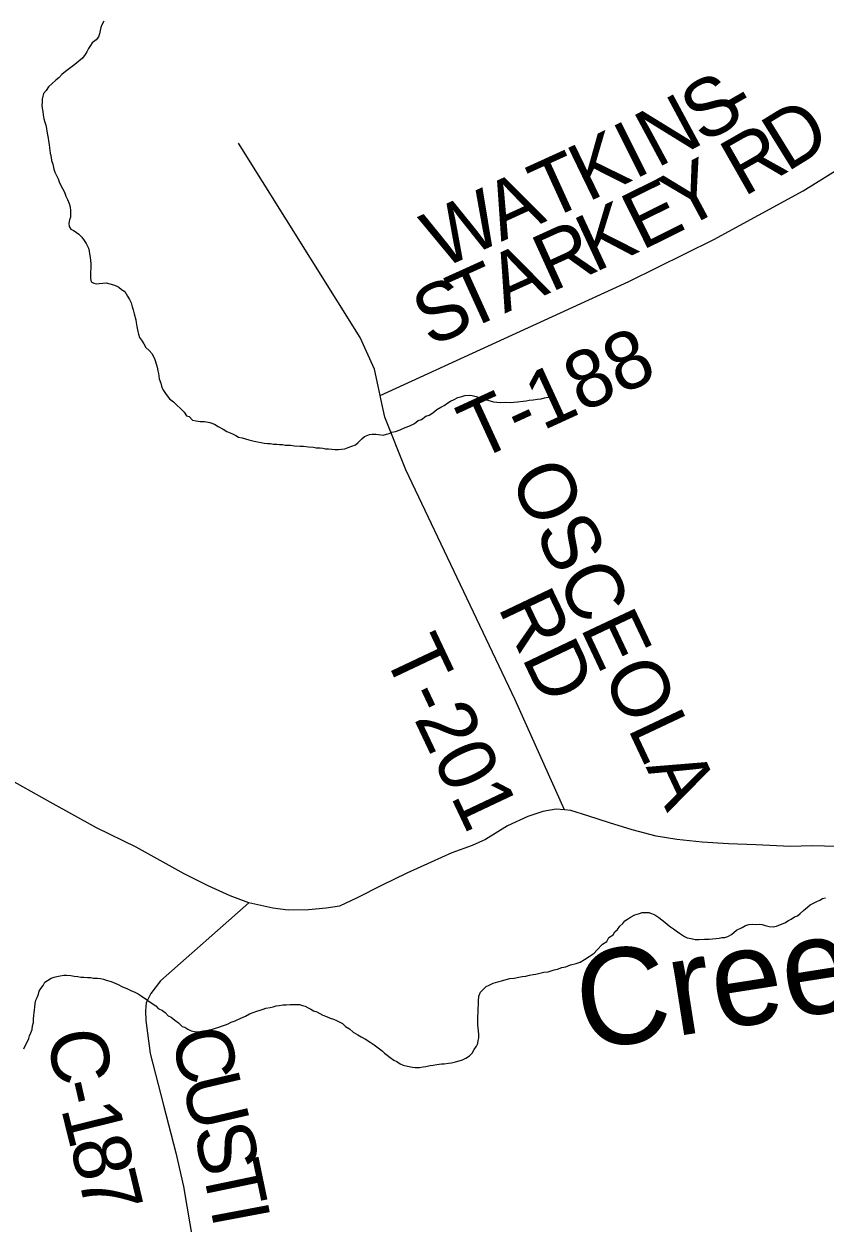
# Model space of a CAD drawing. Extents: x 1310247 to 1664935, y 284496 to 704931.
# Drawn here: x 1532360 to 1536534, y 478494 to 484741 of the extents above; entities that cross this region are included whole.
import ezdxf

# ---------------------------------------------------------------- set-up
doc = ezdxf.new("R2010")
doc.units = 0
for name, color, linetype in [('GM_X_County_Road_Text', 7, 'Continuous'), ('GM_X_County_Subdivision_Text', 7, 'Continuous'), ('GM_X_Interstate_Shield', 7, 'Continuous'), ('GM_X_Minor_Lake_Text', 7, 'Continuous'), ('GM_X_Minor_River_Text', 7, 'Continuous'), ('GM_X_Township_Road', 7, 'Continuous'), ('GM_X_Township_Subdivision', 7, 'Continuous')]:
    doc.layers.add(name, color=color, linetype=linetype)

msp = doc.modelspace()

# ---------------------------------------------------------------- linework, layer by layer
at = {"layer": 'GM_X_County_Road_Text'}
msp.add_lwpolyline([(1533530.8, 480162), (1533071, 479755.7), (1533021.5, 479690.4), (1532996.3, 479640.8), (1532993.5, 479598.7), (1532994.4, 479548.5), (1533017, 479377.6), (1533087.7, 479107.3), (1533150.9, 478859.2), (1533191.5, 478683.8), (1533241.6, 478387.9), (1533278.3, 478220.6), (1533348.3, 478040.9), (1533474.4, 477797.3), (1534173.6, 476597.1), (1537612.9, 470693.1)], dxfattribs=at)
at = {"layer": 'GM_X_County_Subdivision_Text'}
for points in [[(1534215.7, 482805.9), (1535511.9, 483398.7), (1535955.2, 483618.4), (1536419.1, 483871.9), (1536599.6, 483983.4), (1536717.8, 484091.9), (1536773.5, 484189.3), (1536863, 484260.1), (1537210.2, 484369), (1537644, 484625)], [(1534205.6, 482853.7), (1534187.1, 482941.9), (1534111.4, 483107.6), (1533478.3, 484120.1)], [(1535176.4, 480646.2), (1534919.6, 481219.8), (1534349.7, 482418), (1534239.5, 482692.4), (1534219.6, 482787.2), (1534215.7, 482805.9), (1534205.6, 482853.7)]]:
    msp.add_lwpolyline(points, dxfattribs=at)
at = {"layer": 'GM_X_Interstate_Shield'}
msp.add_lwpolyline([(1536596.3, 480455.1), (1536465.4, 480458.8), (1536354.6, 480455.9), (1536173.6, 480465), (1536030.7, 480469), (1535894, 480478.9), (1535761.5, 480492.6), (1535653.2, 480509.7), (1535529.3, 480543.3), (1535411.5, 480578.8), (1535297.7, 480616.1), (1535209.9, 480642.6), (1535176.4, 480646.2), (1535133.6, 480650.8), (1535062.7, 480638.8), (1534985.5, 480612.8), (1534879.3, 480563.6), (1534764.6, 480492.6), (1534695.2, 480460.4), (1534589.4, 480423.3), (1534481.3, 480374.1), (1534354.8, 480317.4), (1534222.1, 480252.9), (1534095.4, 480188.2), (1534003.5, 480144.6), (1533934.8, 480134.5), (1533841.9, 480125.1), (1533737.1, 480124), (1533656.8, 480134.3), (1533530.8, 480162), (1533435.1, 480198.8), (1533319.7, 480250.2), (1533194.7, 480313.9), (1532944.8, 480451.4), (1532738.2, 480553.6), (1532496.2, 480686.9), (1532254.4, 480822.1)], dxfattribs=at)
at = {"layer": 'GM_X_Minor_River_Text'}
for points in [[(1532775.8, 484754.9), (1532765.3, 484737.1), (1532760.9, 484723.2), (1532756.5, 484707.2), (1532754, 484689.2), (1532747.6, 484673.3), (1532735.2, 484657.6), (1532714.7, 484642), (1532706.3, 484628.2), (1532695.9, 484612.4), (1532687.5, 484596.5), (1532679.1, 484582.7), (1532664.5, 484563), (1532646, 484547.3), (1532625.5, 484529.8), (1532611.2, 484520.1), (1532596.9, 484508.4), (1532576.4, 484492.8), (1532557.9, 484477.2), (1532541.4, 484459.6), (1532525.1, 484447.9), (1532506.5, 484430.3), (1532488, 484412.7), (1532475.5, 484395), (1532461.1, 484379.3), (1532458.7, 484365.3), (1532454.3, 484349.3), (1532453.9, 484333.3), (1532453.5, 484317.2), (1532455.2, 484303.2), (1532458.7, 484285), (1532460.3, 484266.9), (1532463.8, 484246.8), (1532469.4, 484228.6), (1532473, 484214.4), (1532476.6, 484196.3), (1532478.3, 484182.2), (1532481.8, 484164.1), (1532485.4, 484145.9), (1532487, 484131.8), (1532490.6, 484113.7), (1532492.2, 484095.6), (1532493.8, 484081.5), (1532495.5, 484067.4), (1532501, 484045.2), (1532502.6, 484029.1), (1532510.2, 484010.9), (1532515.5, 483984.7), (1532521.2, 483968.5), (1532526.8, 483954.3), (1532538.4, 483934), (1532544, 483917.8), (1532551.6, 483899.5), (1532561.2, 483883.3), (1532570.8, 483865), (1532578.4, 483844.7), (1532585.9, 483826.5), (1532595.5, 483806.2), (1532601, 483788), (1532602.6, 483767.9), (1532602.1, 483747.8), (1532601.7, 483733.8), (1532597.3, 483719.9), (1532592.9, 483703.9), (1532594.5, 483685.8), (1532604.2, 483671.5), (1532622, 483663.1), (1532645.7, 483646.5)], [(1532645.7, 483646.5), (1532661.4, 483630), (1532673, 483613.7), (1532684.7, 483597.4), (1532696.1, 483573), (1532699.8, 483556.9), (1532701.4, 483542.8), (1532705, 483524.6), (1532706.6, 483510.6), (1532708.2, 483490.5), (1532707.6, 483466.4), (1532707.2, 483450.3), (1532706.7, 483430.3), (1532706.3, 483414.3), (1532709.9, 483398.1), (1532723.7, 483389.8), (1532737.7, 483387.4), (1532751.8, 483389.1), (1532770, 483390.7), (1532788.1, 483392.2), (1532808.1, 483387.7), (1532826, 483381.3), (1532839.9, 483376.9), (1532853.8, 483370.6), (1532867.6, 483358.2), (1532885.4, 483347.8), (1532898.9, 483323.3), (1532910.5, 483305), (1532918.1, 483288.8), (1532923.6, 483266.6), (1532929.2, 483252.4), (1532934.7, 483230.2), (1532942, 483199.9), (1532943.7, 483185.8), (1532947.2, 483165.7), (1532952.6, 483139.5), (1532956.2, 483125.3), (1532961.8, 483107.1), (1532971.5, 483092.8), (1532985.1, 483074.5), (1532994.7, 483056.2), (1533012.3, 483039.7), (1533028, 483023.3), (1533041.3, 482992.8), (1533048.8, 482970.6), (1533054.4, 482952.4), (1533057.9, 482934.3), (1533061.6, 482920.1), (1533063.3, 482906), (1533064.9, 482892), (1533072.4, 482869.7), (1533077.9, 482847.5), (1533087.5, 482831.2), (1533101.1, 482810.8), (1533118.6, 482788.3), (1533138.3, 482771.8), (1533155.9, 482755.3), (1533175.6, 482736.8), (1533195.2, 482718.3), (1533206.8, 482699.9), (1533220.8, 482695.6), (1533238.4, 482677.1), (1533256.3, 482672.6), (1533278.4, 482670.1), (1533300.5, 482669.6), (1533328.5, 482664.9), (1533352.4, 482656.3), (1533372.1, 482643.8), (1533397.9, 482629.1), (1533417.7, 482618.6), (1533433.6, 482610.2), (1533449.5, 482603.8), (1533463.4, 482597.4), (1533477.3, 482589.1), (1533497.2, 482584.6), (1533531.1, 482573.7), (1533559.1, 482567), (1533577.1, 482564.6), (1533595.1, 482560.1), (1533611.1, 482557.8), (1533629.1, 482555.3), (1533643.1, 482555), (1533659.2, 482552.6), (1533677.2, 482552.1), (1533691.2, 482549.8), (1533707.3, 482549.4), (1533721.3, 482547.1), (1533749.4, 482546.4), (1533769.4, 482543.9), (1533799.5, 482541.2), (1533815.6, 482540.8), (1533841.6, 482538.1), (1533867.7, 482535.5), (1533881.7, 482533.2), (1533903.8, 482532.6), (1533917.8, 482530.3), (1533931.8, 482527.9), (1533945.8, 482527.6), (1533963.8, 482525.2), (1533979.9, 482524.8), (1533998, 482524.3)], [(1533998, 482524.3), (1534014.1, 482526), (1534032.2, 482527.5), (1534048.5, 482535.2), (1534068.7, 482540.7), (1534086.9, 482548.3), (1534101.3, 482560), (1534119.9, 482579.6), (1534134.2, 482591.3), (1534160.6, 482602.7), (1534174.7, 482604.3), (1534192.8, 482603.9), (1534206.8, 482601.6), (1534230.8, 482599), (1534249.1, 482604.6), (1534263.2, 482608.2), (1534277.4, 482613.9), (1534295.6, 482617.5), (1534319.9, 482626.9), (1534346.3, 482638.3), (1534370.7, 482647.8), (1534395.1, 482659.2), (1534413.5, 482674.8), (1534431.7, 482680.4), (1534454.3, 482697.9), (1534470.5, 482703.5), (1534490.9, 482715.1), (1534511.4, 482732.7), (1534531.8, 482744.2), (1534550.1, 482753.8), (1534568.5, 482767.4), (1534582.8, 482775.1), (1534601.1, 482784.7), (1534621.4, 482794.2), (1534641.6, 482799.8), (1534657.8, 482805.4), (1534680, 482806.8), (1534696, 482804.5), (1534716, 482800), (1534735.9, 482793.5), (1534761.8, 482784.8), (1534777.7, 482780.4), (1534805.7, 482771.7), (1534823.7, 482771.3), (1534843.7, 482768.8), (1534867.9, 482770.2), (1534894, 482769.6), (1534912.1, 482771.1), (1534932.2, 482772.7), (1534960.4, 482776), (1534976.6, 482777.6), (1534992.7, 482781.2), (1535012.8, 482782.8), (1535035, 482786.2), (1535055.1, 482787.8), (1535071.4, 482793.4), (1535091.5, 482796.9), (1535105.7, 482800.6)], [(1536028.2, 479987.3), (1536046.6, 479996.9), (1536073.3, 480020.3), (1536101.7, 480033.7), (1536120, 480043.2), (1536136.2, 480048.9), (1536154.4, 480050.5), (1536176.5, 480049.9), (1536192.6, 480051.5), (1536206.6, 480049.2), (1536222.5, 480044.8), (1536242.5, 480038.3), (1536264.5, 480037.8), (1536280.7, 480041.4), (1536301, 480048.9), (1536325.3, 480058.4), (1536343.7, 480070), (1536357.9, 480077.6), (1536374.3, 480089.3), (1536390.5, 480094.9), (1536404.9, 480106.6), (1536421.3, 480122.3), (1536441.8, 480139.8), (1536456.2, 480151.5), (1536474.5, 480161.1), (1536490.8, 480168.7), (1536507, 480176.4), (1536521.3, 480184.1), (1536535.5, 480187.7)], [(1534398.1, 479304.3), (1534420.2, 479303.7), (1534440.4, 479307.2), (1534454.5, 479308.9), (1534476.7, 479314.4), (1534492.8, 479316), (1534511, 479319.6), (1534535.2, 479323), (1534549.2, 479322.7), (1534571.4, 479326.2), (1534587.5, 479327.8), (1534607.8, 479333.3), (1534628, 479338.8), (1534644.2, 479344.5), (1534662.5, 479352.1), (1534680.9, 479365.7), (1534695.3, 479379.4), (1534705.8, 479397.2), (1534718.3, 479414.9), (1534724.6, 479428.8), (1534727.1, 479444.8), (1534729.4, 479458.8), (1534729.9, 479476.8), (1534728.3, 479494.9), (1534726.7, 479511), (1534725.1, 479527.1), (1534725.5, 479545.2), (1534724.2, 479571.3), (1534726.6, 479589.3), (1534727.2, 479613.3), (1534727.7, 479631.4), (1534728.1, 479649.4), (1534730.8, 479675.5), (1534739.4, 479697.3), (1534753.8, 479713), (1534768.2, 479726.7), (1534784.4, 479732.4), (1534804.8, 479743.9), (1534829.1, 479751.3), (1534855.3, 479756.7), (1534871.6, 479762.4), (1534891.8, 479767.9), (1534913.9, 479769.4), (1534938.2, 479774.8), (1534956.3, 479778.4), (1534974.4, 479780), (1534994.7, 479785.5), (1535012.8, 479789.1), (1535026.9, 479790.7), (1535041.1, 479794.4), (1535069.4, 479801.7), (1535091.5, 479803.2), (1535121.9, 479812.5), (1535140.1, 479816.1), (1535162.4, 479825.6), (1535182.6, 479829.1), (1535206.9, 479838.5), (1535237.2, 479845.8), (1535257.5, 479853.4), (1535280, 479866.9), (1535304.4, 479882.3), (1535331, 479899.8), (1535345.4, 479915.5), (1535374.3, 479946.9), (1535396.8, 479960.4), (1535407.4, 479982.2), (1535429.8, 479995.7), (1535438.2, 480011.5), (1535452.6, 480023.2), (1535465.1, 480041), (1535479.5, 480054.7), (1535489.9, 480068.5), (1535504.1, 480076.2), (1535520.5, 480087.8), (1535542.9, 480099.3), (1535567.2, 480106.8), (1535581.4, 480112.4), (1535595.4, 480112.1), (1535615.5, 480111.6), (1535629.4, 480107.3), (1535647.3, 480098.8), (1535667.1, 480086.3), (1535682.9, 480073.9), (1535698.6, 480061.4), (1535712.4, 480049.1), (1535728.1, 480036.7), (1535744, 480026.2), (1535757.8, 480015.9), (1535775.5, 480003.4), (1535801.2, 479986.7), (1535815.1, 479980.4), (1535837.1, 479975.8), (1535857.1, 479971.3), (1535877.2, 479970.9), (1535905.3, 479972.2), (1535929.5, 479973.6), (1535947.6, 479975.2), (1535981.8, 479978.4), (1535996, 479982), (1536012, 479981.6), (1536028.2, 479987.3)], [(1532359.5, 479401.6), (1532370.1, 479423.4), (1532378.5, 479439.3), (1532384.9, 479455.2), (1532389.3, 479469.1), (1532395.7, 479485), (1532402.2, 479502.9), (1532404.6, 479520.9), (1532409.1, 479538.9), (1532409.5, 479556.9), (1532412, 479574.9), (1532412.3, 479589), (1532414.7, 479604.9), (1532417.1, 479618.9), (1532417.5, 479637), (1532422, 479654.9), (1532428.4, 479668.8), (1532434.9, 479686.7), (1532439.3, 479702.7), (1532447.6, 479716.5), (1532460.1, 479732.3), (1532468.5, 479748.1), (1532482.8, 479757.8), (1532501.2, 479769.4), (1532517.4, 479775), (1532531.6, 479778.7), (1532547.7, 479782.3)], [(1532547.7, 479782.3), (1532567.9, 479785.8), (1532582, 479785.5), (1532604, 479783), (1532622, 479780.5), (1532640, 479778.1), (1532656, 479775.7), (1532672.1, 479775.3), (1532690.1, 479772.9), (1532708.2, 479772.4), (1532722.2, 479770.1), (1532742.3, 479769.6), (1532758.3, 479767.2), (1532774.3, 479764.8), (1532788.2, 479758.5), (1532814.2, 479751.8), (1532849.9, 479736.9), (1532869.8, 479726.4), (1532899.6, 479713.6), (1532919.4, 479703.1), (1532933.4, 479698.8), (1532955.2, 479688.2), (1532971, 479677.8), (1532998.7, 479659.1), (1533012.5, 479648.7), (1533046.1, 479625.8), (1533059.8, 479611.5), (1533081.6, 479600.9), (1533095.4, 479590.5), (1533111.1, 479574.1), (1533126.9, 479565.7), (1533146.7, 479551.2), (1533164.4, 479536.7), (1533184, 479518.1), (1533198, 479513.8), (1533213.8, 479503.4), (1533231.7, 479494.9), (1533247.7, 479492.5), (1533261.7, 479490.2), (1533277.8, 479491.8), (1533297.9, 479493.3), (1533324.2, 479500.7), (1533342.4, 479504.3), (1533358.6, 479509.9), (1533374.8, 479513.6), (1533388.9, 479519.2), (1533409.2, 479526.8), (1533423.4, 479532.5), (1533439.7, 479540.1), (1533460, 479547.6), (1533490.4, 479560.9), (1533514.8, 479572.4), (1533535.2, 479583.9), (1533573.7, 479597), (1533589.9, 479602.7), (1533606.1, 479608.3), (1533620.3, 479614), (1533642.5, 479617.5), (1533658.7, 479621.1), (1533674.8, 479624.7), (1533688.9, 479626.4), (1533709.1, 479629.9), (1533725.2, 479631.5), (1533747.4, 479633), (1533765.4, 479632.5), (1533779.5, 479632.2), (1533795.5, 479631.8), (1533811.5, 479627.4), (1533825.5, 479623.1), (1533841.3, 479614.7), (1533855.2, 479608.3), (1533869.1, 479600), (1533885, 479593.5), (1533900.9, 479585.1), (1533916.7, 479576.7), (1533936.6, 479570.2), (1533954.5, 479561.8), (1533972.4, 479555.3), (1533988.3, 479548.9), (1534002.3, 479542.5), (1534020.1, 479534.1), (1534035.8, 479517.7), (1534055.6, 479505.2), (1534075.2, 479488.6), (1534099, 479474), (1534116.8, 479463.5), (1534138.6, 479451), (1534164.3, 479436.3), (1534184.1, 479421.8), (1534205.8, 479407.2), (1534225.5, 479390.7), (1534239.2, 479378.3), (1534253, 479368), (1534268.8, 479355.5), (1534286.6, 479343.1), (1534302.4, 479334.7), (1534320.3, 479324.2), (1534336.1, 479315.8), (1534358.1, 479311.2), (1534384.1, 479306.6), (1534398.1, 479304.3)]]:
    msp.add_lwpolyline(points, dxfattribs=at)

# ---------------------------------------------------------------- texts
at = {"layer": 'GM_X_Minor_Lake_Text'}
msp.add_text('Creek', height=499.98, rotation=8.91251, dxfattribs=at).set_placement((1535276.9, 479391.6))
at = {"layer": 'GM_X_Township_Road'}
for s, rotation, p in [('C', 278.3978, (1532482.6, 479485.5)), ('C', 283.25528, (1533124.2, 479478.7)), ('U', 283.25346, (1533180.7, 479238.9)), ('-', 282.91941, (1532523.3, 479216.4)), ('1', 283.87301, (1532552.1, 479091)), ('S', 283.00139, (1533241.1, 478982.2)), ('8', 283.92591, (1532596.5, 478911.3)), ('T', 281.78735, (1533286.3, 478786.6)), ('7', 283.53136, (1532640.9, 478732.5)), ('I', 280.66235, (1533331.8, 478568.5))]:
    msp.add_text(s, height=300, rotation=rotation, dxfattribs=at).set_placement(p)
at = {"layer": 'GM_X_Township_Subdivision'}
for s, rotation, p in [('S', 29.1143, (1535894.2, 484115)), ('N', 28.2714, (1535657.5, 483987.7)), ('-', 29.73881, (1536074.2, 484215.3)), ('D', 31.80411, (1536334.1, 483966.1)), ('I', 26.57901, (1535538.7, 483928.1)), ('K', 25.83941, (1535297.3, 483811.2)), ('R', 29.62806, (1536109.2, 483838)), ('T', 24.51383, (1535086.3, 483714.8)), ('Y', 28.2714, (1535789.4, 483663.7)), ('A', 24.51695, (1534846.1, 483605.3)), ('E', 26.37843, (1535578.8, 483559.1)), ('W', 24.51196, (1534529.8, 483461.1)), ('K', 24.93901, (1535332, 483444.2)), ('R', 24.47034, (1535105.3, 483341)), ('A', 24.40702, (1534864.6, 483231.8)), ('T', 24.40458, (1534660.2, 483139)), ('S', 24.40778, (1534475.9, 483055.4)), ('T-188', 24.67744, (1534718.3, 482462.7)), ('OSCEOLA', 295.23255, (1534885.6, 482383)), ('RD', 295.46311, (1534826.4, 481702.9)), ('T-201', 295.31823, (1534228, 481464))]:
    msp.add_text(s, height=300, rotation=rotation, dxfattribs=at).set_placement(p)

doc.saveas('drawing.dxf')
